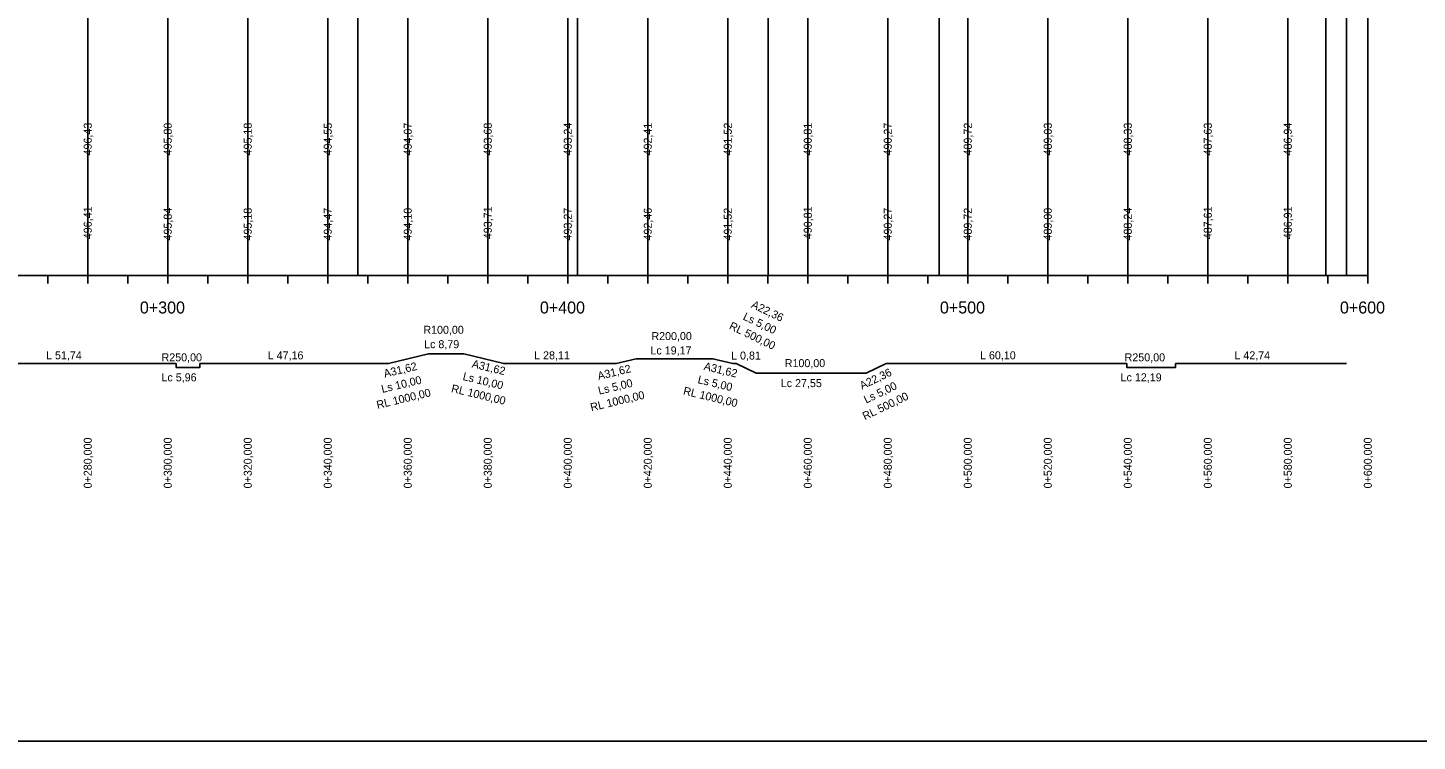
# Model space of a CAD drawing. Extents: x -632716 to -629545, y -1094726 to -1088285.
# Drawn here: x -632178.9 to -631831.5, y -1089552.8 to -1089374.5 of the extents above; entities that cross this region are included whole.
import ezdxf

# ---------------------------------------------------------------- set-up
doc = ezdxf.new("R2010")
doc.units = 0
for name, color, linetype in [('20', 7, 'Continuous'), ('formát', 7, 'Continuous'), ('NIVELETA_VYSKY', 7, 'Continuous'), ('REZ_POPIS', 7, 'Continuous'), ('REZ_TABULKA', 7, 'Continuous'), ('REZ_TENKA', 7, 'Continuous'), ('REZ_TLUSTA', 7, 'Continuous'), ('SKLONY_NIVELETA', 7, 'Continuous'), ('TEREN_VYSKY', 7, 'Continuous')]:
    doc.layers.add(name, color=color, linetype=linetype)

msp = doc.modelspace()

# ---------------------------------------------------------------- linework, layer by layer
at = {"layer": '20'}
for points in [[(-631843.88, -1089136.44), (-631843.88, -1089386.44), (-631843.88, -1089436.44), (-631843.88, -1089376.44)], [(-632163.88, -1089272.15), (-632163.88, -1089386.44), (-632163.88, -1089436.44), (-632163.88, -1089376.44)], [(-632143.88, -1089278.41), (-632143.88, -1089386.44), (-632143.88, -1089436.44), (-632143.88, -1089376.44)], [(-632123.88, -1089284.66), (-632123.88, -1089386.44), (-632123.88, -1089436.44), (-632123.88, -1089376.44)], [(-632103.88, -1089290.92), (-632103.88, -1089386.44), (-632103.88, -1089436.44), (-632103.88, -1089376.44)], [(-632083.88, -1089295.71), (-632083.88, -1089386.44), (-632083.88, -1089436.44), (-632083.88, -1089376.44)], [(-632063.88, -1089299.63), (-632063.88, -1089386.44), (-632063.88, -1089436.44), (-632063.88, -1089376.44)], [(-632043.88, -1089304.02), (-632043.88, -1089386.44), (-632043.88, -1089436.44), (-632043.88, -1089376.44)], [(-632023.88, -1089312.37), (-632023.88, -1089386.44), (-632023.88, -1089436.44), (-632023.88, -1089376.44)], [(-632003.88, -1089321.27), (-632003.88, -1089386.44), (-632003.88, -1089436.44), (-632003.88, -1089376.44)], [(-631983.88, -1089328.38), (-631983.88, -1089386.44), (-631983.88, -1089436.44), (-631983.88, -1089376.44)], [(-631963.88, -1089333.7), (-631963.88, -1089386.44), (-631963.88, -1089436.44), (-631963.88, -1089376.44)], [(-631943.88, -1089339.21), (-631943.88, -1089386.44), (-631943.88, -1089436.44), (-631943.88, -1089376.44)], [(-631923.88, -1089346.17), (-631923.88, -1089386.44), (-631923.88, -1089436.44), (-631923.88, -1089376.44)], [(-631903.88, -1089353.13), (-631903.88, -1089386.44), (-631903.88, -1089436.44), (-631903.88, -1089376.44)], [(-631883.88, -1089360.1), (-631883.88, -1089386.44), (-631883.88, -1089436.44), (-631883.88, -1089376.44)], [(-631863.88, -1089367.06), (-631863.88, -1089386.44), (-631863.88, -1089436.44), (-631863.88, -1089376.44)]]:
    msp.add_lwpolyline(points, dxfattribs=at)
at = {"layer": 'formát'}
msp.add_lwpolyline([(-632543.13, -1089552.83), (-631403.32, -1089552.83), (-631403.32, -1088958.83), (-632543.13, -1088958.83)], close=True, dxfattribs=at)
at = {"layer": 'REZ_TABULKA'}
msp.add_lwpolyline([(-632193.53, -1089458.44), (-632141.79, -1089458.44), (-632141.79, -1089459.4), (-632135.83, -1089459.4), (-632135.83, -1089458.44), (-632088.67, -1089458.44), (-632088.67, -1089458.44), (-632078.67, -1089456.04), (-632078.67, -1089456.04), (-632069.88, -1089456.04), (-632069.88, -1089456.04), (-632059.88, -1089458.44), (-632059.88, -1089458.44), (-632031.76, -1089458.44), (-632031.76, -1089458.44), (-632026.76, -1089457.24), (-632026.76, -1089457.24), (-632007.59, -1089457.24), (-632007.59, -1089457.24), (-632002.59, -1089458.44), (-632002.59, -1089458.44), (-632001.78, -1089458.44), (-632001.78, -1089458.44), (-631996.78, -1089460.84), (-631996.78, -1089460.84), (-631969.24, -1089460.84), (-631969.24, -1089460.84), (-631964.24, -1089458.44), (-631964.24, -1089458.44), (-631904.14, -1089458.44), (-631904.14, -1089459.4), (-631891.95, -1089459.4), (-631891.95, -1089458.44), (-631849.22, -1089458.44)], dxfattribs=at)
at = {"layer": 'REZ_TENKA'}
for p, q in [((-632173.88, -1089438.44), (-632173.88, -1089436.44)), ((-632163.88, -1089438.44), (-632163.88, -1089436.44)), ((-632153.88, -1089438.44), (-632153.88, -1089436.44)), ((-632133.88, -1089438.44), (-632133.88, -1089436.44)), ((-632123.88, -1089438.44), (-632123.88, -1089436.44)), ((-632113.88, -1089438.44), (-632113.88, -1089436.44)), ((-632103.88, -1089438.44), (-632103.88, -1089436.44)), ((-632093.88, -1089438.44), (-632093.88, -1089436.44)), ((-632083.88, -1089438.44), (-632083.88, -1089436.44)), ((-632073.88, -1089438.44), (-632073.88, -1089436.44)), ((-632063.88, -1089438.44), (-632063.88, -1089436.44)), ((-632053.88, -1089438.44), (-632053.88, -1089436.44)), ((-632033.88, -1089438.44), (-632033.88, -1089436.44)), ((-632023.88, -1089438.44), (-632023.88, -1089436.44)), ((-632013.88, -1089438.44), (-632013.88, -1089436.44)), ((-632003.88, -1089438.44), (-632003.88, -1089436.44)), ((-631993.88, -1089438.44), (-631993.88, -1089436.44)), ((-631983.88, -1089438.44), (-631983.88, -1089436.44)), ((-631973.88, -1089438.44), (-631973.88, -1089436.44)), ((-631963.88, -1089438.44), (-631963.88, -1089436.44)), ((-631953.88, -1089438.44), (-631953.88, -1089436.44)), ((-631933.88, -1089438.44), (-631933.88, -1089436.44)), ((-631923.88, -1089438.44), (-631923.88, -1089436.44)), ((-631913.88, -1089438.44), (-631913.88, -1089436.44)), ((-631903.88, -1089438.44), (-631903.88, -1089436.44)), ((-631893.88, -1089438.44), (-631893.88, -1089436.44)), ((-631883.88, -1089438.44), (-631883.88, -1089436.44)), ((-631873.88, -1089438.44), (-631873.88, -1089436.44)), ((-631863.88, -1089438.44), (-631863.88, -1089436.44)), ((-631853.88, -1089438.44), (-631853.88, -1089436.44))]:
    msp.add_line(p, q, dxfattribs=at)
at = {"layer": 'REZ_TLUSTA'}
for p, q in [((-632443.88, -1089436.44), (-631843.88, -1089436.44)), ((-632143.88, -1089438.44), (-632143.88, -1089434.44)), ((-632043.88, -1089438.44), (-632043.88, -1089434.44)), ((-631943.88, -1089438.44), (-631943.88, -1089434.44)), ((-631843.88, -1089438.44), (-631843.88, -1089434.44))]:
    msp.add_line(p, q, dxfattribs=at)
at = {"layer": 'SKLONY_NIVELETA'}
for p, q in [((-632096.38, -1089193.27), (-632096.38, -1089436.44)), ((-632041.41, -1089204.03), (-632041.41, -1089436.44)), ((-631993.77, -1089226.68), (-631993.77, -1089436.44)), ((-631951.07, -1089236.71), (-631951.07, -1089436.44)), ((-631854.39, -1089270.36), (-631854.39, -1089436.44)), ((-631849.22, -1089270.45), (-631849.22, -1089436.44))]:
    msp.add_line(p, q, dxfattribs=at)

# ---------------------------------------------------------------- texts
at = {"layer": 'NIVELETA_VYSKY'}
for s, p in [('496,43', (-632162.88, -1089406.44)), ('495,80', (-632142.88, -1089406.44)), ('495,18', (-632122.88, -1089406.44)), ('494,55', (-632102.88, -1089406.44)), ('494,07', (-632082.88, -1089406.44)), ('493,68', (-632062.88, -1089406.44)), ('493,24', (-632042.88, -1089406.44)), ('492,41', (-632022.88, -1089406.44)), ('491,52', (-632002.88, -1089406.44)), ('490,81', (-631982.88, -1089406.44)), ('490,27', (-631962.88, -1089406.44)), ('489,72', (-631942.88, -1089406.44)), ('489,03', (-631922.88, -1089406.44)), ('488,33', (-631902.88, -1089406.44)), ('487,63', (-631882.88, -1089406.44)), ('486,94', (-631862.88, -1089406.44))]:
    msp.add_text(s, height=2, rotation=90, dxfattribs=at).set_placement(p)
at = {"layer": 'REZ_POPIS'}
for s, p in [('0+300', (-632150.84, -1089445.94)), ('0+400', (-632050.84, -1089445.94)), ('0+500', (-631950.84, -1089445.94)), ('0+600', (-631850.84, -1089445.94))]:
    msp.add_text(s, height=3, dxfattribs=at).set_placement(p)
at = {"layer": 'REZ_TABULKA'}
for s, rotation, p in [('A22,36', 334.359, (-631998.18, -1089444.38)), ('Ls 5,00', 334.359, (-632000.25, -1089447.38)), ('RL 500,00', 334.359, (-632003.7, -1089449.72)), ('A31,62', 346.5043, (-632067.99, -1089459.39)), ('A31,62', 13.4957, (-632089.63, -1089461.97)), ('Ls 10,00', 346.5043, (-632070.26, -1089462.54)), ('A31,62', 13.4957, (-632036.17, -1089462.57)), ('A31,62', 346.5043, (-632010, -1089459.99)), ('A22,36', 25.641, (-631970.32, -1089464.99)), ('Ls 10,00', 13.4957, (-632090.23, -1089465.81)), ('RL 1000,00', 346.5043, (-632073.14, -1089465.55)), ('Ls 5,00', 13.4957, (-632036.03, -1089466.24)), ('RL 1000,00', 346.5043, (-632015.15, -1089466.15)), ('Ls 5,00', 346.5043, (-632011.53, -1089463.32)), ('Ls 5,00', 25.641, (-631969.28, -1089468.48)), ('RL 1000,00', 13.4957, (-632091.42, -1089469.8)), ('RL 1000,00', 13.4957, (-632037.97, -1089470.4)), ('RL 500,00', 25.641, (-631969.61, -1089472.63)), ('0+280,000', 90, (-632162.88, -1089489.65)), ('0+300,000', 90, (-632142.88, -1089489.65)), ('0+320,000', 90, (-632122.88, -1089489.65)), ('0+340,000', 90, (-632102.88, -1089489.65)), ('0+360,000', 90, (-632082.88, -1089489.65)), ('0+380,000', 90, (-632062.88, -1089489.65)), ('0+400,000', 90, (-632042.88, -1089489.65)), ('0+420,000', 90, (-632022.88, -1089489.65)), ('0+440,000', 90, (-632002.88, -1089489.65)), ('0+460,000', 90, (-631982.88, -1089489.65)), ('0+480,000', 90, (-631962.88, -1089489.65)), ('0+500,000', 90, (-631942.88, -1089489.65)), ('0+520,000', 90, (-631922.88, -1089489.65)), ('0+540,000', 90, (-631902.88, -1089489.65)), ('0+560,000', 90, (-631882.88, -1089489.65)), ('0+580,000', 90, (-631862.88, -1089489.65)), ('0+600,000', 90, (-631842.88, -1089489.65))]:
    msp.add_text(s, height=2, rotation=rotation, dxfattribs=at).set_placement(p)
for s, p in [('R100,00', (-632079.98, -1089451.01)), ('R200,00', (-632022.97, -1089452.58)), ('Lc 8,79', (-632079.79, -1089454.61)), ('Lc 19,17', (-632023.21, -1089456.18)), ('L 51,74', (-632174.29, -1089457.39)), ('R250,00', (-632145.43, -1089457.9)), ('L 47,16', (-632118.88, -1089457.39)), ('L 28,11', (-632052.28, -1089457.39)), ('L 0,81', (-632003.04, -1089457.45)), ('R100,00', (-631989.63, -1089459.34)), ('L 60,10', (-631940.82, -1089457.39)), ('R250,00', (-631904.67, -1089457.9)), ('L 42,74', (-631877.22, -1089457.39)), ('Lc 5,96', (-632145.44, -1089462.9)), ('Lc 12,19', (-631905.67, -1089462.9)), ('Lc 27,55', (-631990.63, -1089464.34))]:
    msp.add_text(s, height=2, dxfattribs=at).set_placement(p)
at = {"layer": 'TEREN_VYSKY'}
for s, p in [('496,41', (-632162.88, -1089427.37)), ('493,71', (-632062.88, -1089427.37)), ('490,81', (-631982.88, -1089427.37)), ('487,61', (-631882.88, -1089427.37)), ('486,91', (-631862.88, -1089427.37)), ('495,84', (-632142.88, -1089427.7)), ('495,18', (-632122.88, -1089427.7)), ('494,47', (-632102.88, -1089427.7)), ('494,10', (-632082.88, -1089427.7)), ('493,27', (-632042.88, -1089427.7)), ('492,46', (-632022.88, -1089427.7)), ('491,52', (-632002.88, -1089427.7)), ('490,27', (-631962.88, -1089427.7)), ('489,72', (-631942.88, -1089427.7)), ('489,00', (-631922.88, -1089427.7)), ('488,24', (-631902.88, -1089427.7))]:
    msp.add_text(s, height=2, rotation=90, dxfattribs=at).set_placement(p)

doc.saveas('drawing.dxf')
